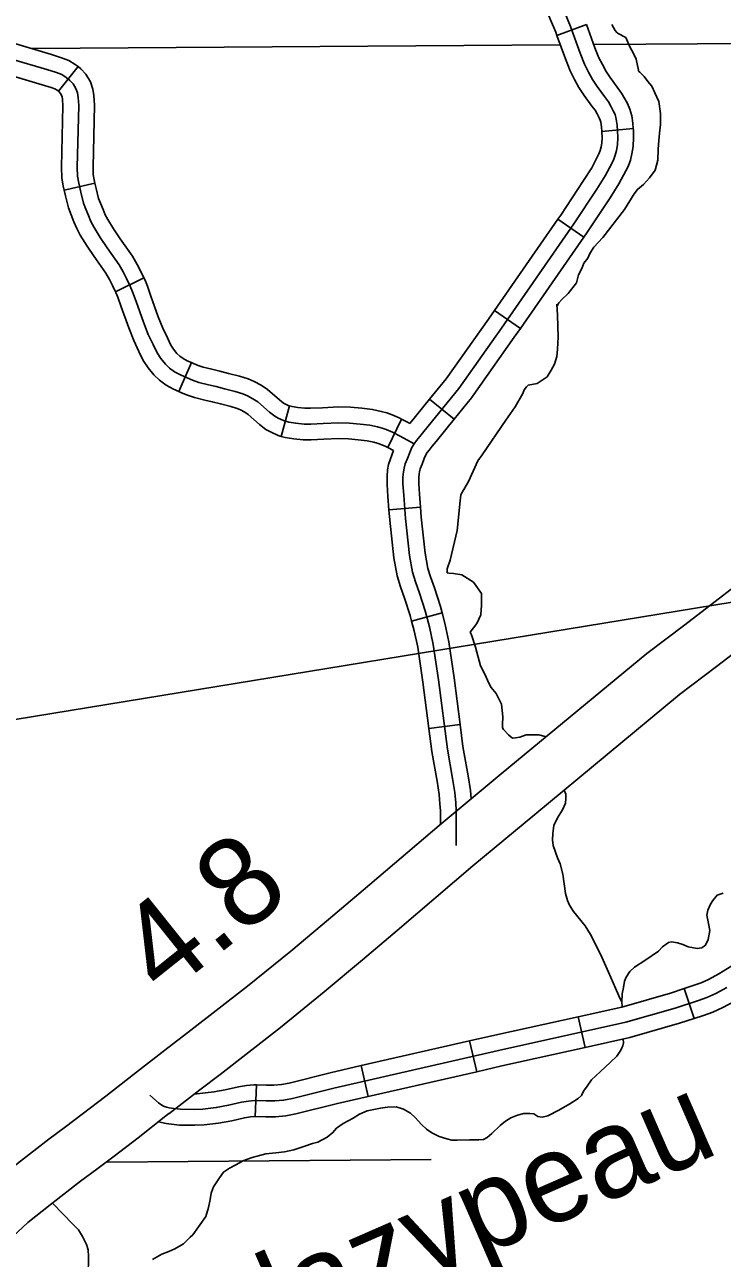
# Model space of a CAD drawing. Extents: x -3711 to 825, y -151 to 1050.
# Drawn here: x -2712.6 to -2675.5, y 376.3 to 442 of the extents above; entities that cross this region are included whole.
import ezdxf

# ---------------------------------------------------------------- set-up
doc = ezdxf.new("R2010")
doc.units = 0
for name, color, linetype in [('Level 10', 7, 'Continuous'), ('Level 32', 7, 'Continuous'), ('Level 35', 7, 'Continuous'), ('Level 48', 7, 'Continuous'), ('Level 5', 7, 'Continuous'), ('R_Dimension', 7, 'Continuous')]:
    doc.layers.add(name, color=color, linetype=linetype)

msp = doc.modelspace()

# ---------------------------------------------------------------- linework, layer by layer
at = {"layer": 'Level 10'}
for p, q in [((-2706.669, 386.248), (-2706.663, 386.253)), ((-2704.949, 384.036), (-2704.943, 384.041))]:
    msp.add_line(p, q, dxfattribs=at)
for points in [[(-2706.663, 386.253), (-2704.999, 387.54), (-2703.925, 388.355), (-2700.75, 390.822), (-2698.456, 392.689), (-2696.451, 394.375), (-2694.609, 395.932), (-2690.561, 399.38), (-2687.248, 402.122), (-2679.507, 408.541), (-2677.486, 410.069), (-2673.235, 413.332)], [(-2671.476, 411.15), (-2675.788, 407.84), (-2677.767, 406.344), (-2685.461, 399.964), (-2688.759, 397.234), (-2692.796, 393.796), (-2694.644, 392.233), (-2696.67, 390.529), (-2699.005, 388.629), (-2702.218, 386.132), (-2703.295, 385.315), (-2704.949, 384.036)], [(-2722.587, 372.439), (-2718.159, 376.666), (-2716.385, 378.412), (-2715.441, 379.293), (-2714.273, 380.373), (-2713, 381.381), (-2711.341, 382.678), (-2710.445, 383.333), (-2709.555, 384.005), (-2708.303, 384.971), (-2706.828, 386.124), (-2706.669, 386.248)], [(-2704.943, 384.041), (-2705.102, 383.917), (-2706.584, 382.758), (-2707.856, 381.778), (-2708.774, 381.084), (-2709.651, 380.443), (-2711.267, 379.179), (-2712.45, 378.242), (-2713.534, 377.24), (-2714.446, 376.389), (-2716.208, 374.654)]]:
    msp.add_lwpolyline(points, dxfattribs=at)
at = {"layer": 'Level 32'}
for p, q in [((-2684.287, 441.438), (-2682.706, 442.01)), ((-2710.826, 438.463), (-2709.775, 439.775)), ((-2681.9, 436.327), (-2680.226, 436.48)), ((-2710.518, 433.202), (-2708.877, 433.567)), ((-2684.239, 431.653), (-2682.858, 430.694)), ((-2707.778, 427.781), (-2706.274, 428.533)), ((-2687.616, 426.793), (-2686.235, 425.834)), ((-2704.418, 422.483), (-2703.735, 424.02)), ((-2698.968, 420.093), (-2698.518, 421.713)), ((-2691.065, 422.067), (-2689.762, 421.005)), ((-2693.289, 419.495), (-2692.557, 421.008)), ((-2693.227, 416.191), (-2691.551, 416.322)), ((-2692.024, 410.265), (-2690.402, 410.707)), ((-2691.108, 404.541), (-2689.441, 404.756)), ((-2676.992, 389.099), (-2677.516, 390.697)), ((-2682.788, 387.56), (-2683.152, 389.201)), ((-2688.559, 386.272), (-2688.933, 387.911)), ((-2694.329, 384.956), (-2694.703, 386.595)), ((-2700.341, 383.893), (-2700.283, 385.573))]:
    msp.add_line(p, q, dxfattribs=at)
for points in [[(-2687.244, 446.261), (-2686.32, 444.967), (-2685.886, 444.437), (-2685.588, 444.014), (-2685.311, 443.579), (-2685.078, 443.216), (-2684.881, 442.868), (-2684.628, 442.273), (-2684.351, 441.612), (-2684.287, 441.438)], [(-2715.774, 442.024), (-2715.738, 441.759), (-2715.654, 441.391), (-2715.555, 441.095), (-2715.376, 440.736), (-2715.148, 440.469), (-2714.991, 440.288), (-2714.661, 439.996), (-2714.401, 439.801), (-2714.059, 439.567), (-2713.644, 439.397), (-2711.679, 438.814), (-2711.203, 438.663), (-2711.019, 438.593), (-2710.891, 438.515), (-2710.826, 438.463)], [(-2714.109, 442.256), (-2714.082, 442.062), (-2714.033, 441.844), (-2713.998, 441.74), (-2713.964, 441.672), (-2713.873, 441.566), (-2713.793, 441.472), (-2713.598, 441.3), (-2713.421, 441.167), (-2713.256, 441.055), (-2713.085, 440.985), (-2711.186, 440.421), (-2710.65, 440.252), (-2710.274, 440.109), (-2709.923, 439.894), (-2709.775, 439.775)], [(-2683.853, 442.6), (-2683.567, 441.918), (-2683.049, 440.486), (-2682.818, 439.899), (-2682.613, 439.49), (-2682.395, 439.095), (-2682.15, 438.713), (-2681.755, 438.181), (-2681.55, 437.908), (-2681.414, 437.663), (-2681.291, 437.431), (-2681.196, 437.226), (-2681.128, 436.981), (-2681.087, 436.667), (-2681.059, 436.367), (-2681.046, 435.999), (-2681.059, 435.617), (-2681.114, 435.317), (-2681.182, 435.057), (-2681.278, 434.798), (-2681.482, 434.389), (-2681.714, 433.966), (-2682.163, 433.257), (-2683.39, 431.402), (-2687.247, 425.851), (-2689.51, 422.645), (-2691.377, 420.354), (-2691.581, 420.095), (-2691.758, 419.877), (-2691.893, 419.693), (-2692.004, 419.508), (-2692.126, 419.236), (-2692.249, 418.922), (-2692.358, 418.635), (-2692.426, 418.404), (-2692.463, 418.2), (-2692.482, 417.928), (-2692.482, 417.559), (-2692.443, 416.957), (-2692.346, 415.714), (-2692.133, 413.753), (-2691.978, 412.859), (-2691.822, 412.354), (-2691.609, 411.752), (-2691.298, 410.8), (-2691.065, 409.946), (-2690.871, 409.014), (-2690.595, 407.13), (-2690.119, 403.449), (-2689.838, 401.876), (-2689.721, 401.138), (-2689.673, 400.594), (-2689.653, 400.186), (-2689.644, 399.759), (-2689.66, 398.307)], [(-2682.706, 442.01), (-2682.263, 440.783), (-2682.049, 440.242), (-2681.869, 439.881), (-2681.673, 439.525), (-2681.458, 439.191), (-2681.081, 438.684), (-2680.843, 438.366), (-2680.675, 438.063), (-2680.538, 437.805), (-2680.404, 437.518), (-2680.302, 437.148), (-2680.251, 436.759), (-2680.226, 436.48)], [(-2684.287, 441.438), (-2683.836, 440.188), (-2683.586, 439.556), (-2683.358, 439.099), (-2683.118, 438.664), (-2682.842, 438.234), (-2682.428, 437.678), (-2682.257, 437.45), (-2682.153, 437.262), (-2682.044, 437.056), (-2681.987, 436.934), (-2681.953, 436.813), (-2681.922, 436.574), (-2681.9, 436.327)], [(-2713.365, 440.191), (-2711.433, 439.618), (-2710.926, 439.458), (-2710.647, 439.351), (-2710.407, 439.204), (-2710.207, 439.044), (-2710.034, 438.858), (-2709.887, 438.618), (-2709.807, 438.378), (-2709.767, 438.138), (-2709.741, 437.711), (-2709.821, 434.418), (-2709.807, 433.951), (-2709.741, 433.578), (-2709.634, 433.098), (-2709.488, 432.511), (-2709.368, 432.191), (-2709.221, 431.845)], [(-2709.775, 439.775), (-2709.633, 439.662), (-2709.36, 439.368), (-2709.12, 438.974), (-2708.989, 438.581), (-2708.931, 438.233), (-2708.899, 437.727), (-2708.98, 434.42), (-2708.969, 434.037), (-2708.916, 433.743), (-2708.877, 433.567)], [(-2710.826, 438.463), (-2710.781, 438.427), (-2710.707, 438.348), (-2710.655, 438.261), (-2710.626, 438.175), (-2710.604, 438.042), (-2710.582, 437.695), (-2710.662, 434.416), (-2710.646, 433.865), (-2710.565, 433.413), (-2710.518, 433.202)], [(-2681.9, 436.327), (-2681.899, 436.313), (-2681.887, 435.998), (-2681.897, 435.707), (-2681.935, 435.499), (-2681.985, 435.31), (-2682.05, 435.132), (-2682.227, 434.779), (-2682.438, 434.394), (-2682.869, 433.714), (-2684.086, 431.874), (-2684.239, 431.653)], [(-2680.226, 436.48), (-2680.22, 436.42), (-2680.205, 435.999), (-2680.222, 435.526), (-2680.293, 435.134), (-2680.379, 434.805), (-2680.505, 434.464), (-2680.737, 433.999), (-2680.989, 433.539), (-2681.458, 432.8), (-2682.694, 430.93), (-2682.858, 430.694)], [(-2708.877, 433.567), (-2708.816, 433.291), (-2708.684, 432.761), (-2708.587, 432.503), (-2708.446, 432.17), (-2708.326, 431.881), (-2708.198, 431.636), (-2707.891, 431.144), (-2707.529, 430.614), (-2706.886, 429.683), (-2706.63, 429.246), (-2706.444, 428.874), (-2706.274, 428.533)], [(-2710.518, 433.202), (-2710.452, 432.905), (-2710.292, 432.261), (-2710.149, 431.88), (-2709.996, 431.519), (-2709.85, 431.168), (-2709.658, 430.8), (-2709.299, 430.225), (-2708.915, 429.662), (-2708.305, 428.78), (-2708.109, 428.444), (-2707.948, 428.122), (-2707.778, 427.781)], [(-2709.221, 431.845), (-2709.088, 431.525), (-2708.928, 431.218), (-2708.595, 430.685), (-2708.222, 430.138), (-2707.596, 429.231), (-2707.369, 428.845), (-2707.196, 428.498), (-2706.996, 428.098), (-2706.876, 427.791), (-2706.69, 427.272), (-2706.29, 426.165), (-2706.037, 425.525), (-2705.784, 424.978), (-2705.571, 424.538), (-2705.371, 424.232), (-2705.131, 423.938), (-2704.904, 423.725), (-2704.638, 423.525), (-2704.332, 423.365), (-2703.972, 423.205), (-2703.692, 423.085), (-2703.346, 422.965), (-2702.839, 422.845), (-2702.426, 422.752), (-2701.987, 422.632), (-2701.414, 422.485), (-2701.014, 422.365), (-2700.761, 422.258), (-2700.468, 422.098), (-2700.215, 421.925), (-2699.589, 421.378), (-2699.309, 421.165), (-2699.122, 421.058), (-2698.842, 420.93), (-2698.564, 420.853), (-2698.193, 420.791), (-2697.75, 420.752), (-2697.39, 420.752), (-2696.724, 420.779), (-2695.898, 420.819), (-2695.325, 420.805), (-2694.766, 420.752), (-2694.246, 420.685), (-2693.833, 420.605), (-2693.593, 420.539), (-2693.38, 420.459), (-2693.047, 420.312), (-2692.634, 420.112), (-2691.893, 419.693)], [(-2684.239, 431.653), (-2687.616, 426.793)], [(-2682.858, 430.694), (-2686.235, 425.834)], [(-2706.274, 428.533), (-2706.227, 428.44), (-2706.089, 428.087), (-2705.899, 427.556), (-2705.504, 426.462), (-2705.264, 425.856), (-2705.024, 425.338), (-2704.837, 424.953), (-2704.691, 424.729), (-2704.515, 424.513), (-2704.362, 424.369), (-2704.188, 424.238), (-2703.966, 424.122), (-2703.735, 424.02)], [(-2707.778, 427.781), (-2707.765, 427.757), (-2707.664, 427.496), (-2707.481, 426.987), (-2707.076, 425.867), (-2706.81, 425.193), (-2706.544, 424.618), (-2706.304, 424.124), (-2706.05, 423.735), (-2705.747, 423.364), (-2705.447, 423.081), (-2705.088, 422.812), (-2704.697, 422.608), (-2704.418, 422.483)], [(-2687.616, 426.793), (-2687.936, 426.333), (-2690.18, 423.154), (-2691.065, 422.067)], [(-2686.235, 425.834), (-2686.559, 425.369), (-2688.84, 422.137), (-2689.762, 421.005)], [(-2703.735, 424.02), (-2703.635, 423.975), (-2703.388, 423.87), (-2703.111, 423.773), (-2702.65, 423.664), (-2702.223, 423.568), (-2701.772, 423.444), (-2701.189, 423.295), (-2700.729, 423.157), (-2700.396, 423.017), (-2700.028, 422.816), (-2699.699, 422.591), (-2699.057, 422.03), (-2698.843, 421.867), (-2698.738, 421.807), (-2698.553, 421.722), (-2698.518, 421.713)], [(-2704.418, 422.483), (-2704.308, 422.435), (-2703.996, 422.301), (-2703.581, 422.157), (-2703.029, 422.026), (-2702.63, 421.936), (-2702.202, 421.819), (-2701.639, 421.675), (-2701.299, 421.573), (-2701.127, 421.5), (-2700.908, 421.381), (-2700.731, 421.259), (-2700.121, 420.727), (-2699.774, 420.463), (-2699.507, 420.31), (-2699.131, 420.138), (-2698.968, 420.093)], [(-2698.518, 421.713), (-2698.382, 421.675), (-2698.087, 421.626), (-2697.713, 421.592), (-2697.407, 421.592), (-2696.761, 421.618), (-2695.909, 421.66), (-2695.276, 421.645), (-2694.672, 421.587), (-2694.113, 421.516), (-2693.64, 421.424), (-2693.333, 421.339), (-2693.063, 421.237), (-2692.694, 421.075), (-2692.557, 421.008)], [(-2691.065, 422.067), (-2692.112, 420.782)], [(-2692.557, 421.008), (-2692.244, 420.857), (-2692.112, 420.782)], [(-2689.762, 421.005), (-2690.721, 419.828), (-2690.925, 419.57), (-2691.093, 419.363), (-2691.192, 419.228), (-2691.257, 419.119), (-2691.351, 418.91), (-2691.465, 418.619), (-2691.561, 418.367), (-2691.607, 418.21), (-2691.627, 418.096), (-2691.642, 417.898), (-2691.642, 417.586), (-2691.605, 417.017), (-2691.551, 416.322)], [(-2698.968, 420.093), (-2698.746, 420.031), (-2698.3, 419.957), (-2697.787, 419.911), (-2697.374, 419.911), (-2696.687, 419.939), (-2695.888, 419.977), (-2695.375, 419.966), (-2694.859, 419.916), (-2694.38, 419.855), (-2694.026, 419.786), (-2693.854, 419.739), (-2693.698, 419.68), (-2693.4, 419.549), (-2693.289, 419.495)], [(-2692.986, 419.348), (-2693.155, 418.904), (-2693.245, 418.597), (-2693.298, 418.305), (-2693.323, 417.958), (-2693.323, 417.532), (-2693.282, 416.898), (-2693.227, 416.191)], [(-2693.289, 419.495), (-2692.986, 419.348)], [(-2693.227, 416.191), (-2693.183, 415.636), (-2692.966, 413.635), (-2692.797, 412.663), (-2692.621, 412.09), (-2692.405, 411.481), (-2692.104, 410.559), (-2692.024, 410.265)], [(-2691.551, 416.322), (-2691.509, 415.792), (-2691.3, 413.87), (-2691.158, 413.055), (-2691.024, 412.618), (-2690.813, 412.023), (-2690.493, 411.041), (-2690.402, 410.707)], [(-2690.402, 410.707), (-2690.248, 410.142), (-2690.043, 409.16), (-2689.762, 407.245), (-2689.441, 404.756)], [(-2692.024, 410.265), (-2691.883, 409.75), (-2691.699, 408.867), (-2691.427, 407.015), (-2691.108, 404.541)], [(-2691.108, 404.541), (-2690.95, 403.321), (-2690.667, 401.736), (-2690.556, 401.035), (-2690.512, 400.537), (-2690.494, 400.157), (-2690.484, 399.754), (-2690.488, 399.44)], [(-2689.441, 404.756), (-2689.288, 403.577), (-2689.009, 402.015), (-2688.887, 401.241), (-2688.847, 400.798)], [(-2677.516, 390.697), (-2677.031, 390.856), (-2676.618, 391.003), (-2676.213, 391.188), (-2675.663, 391.489), (-2674.981, 391.901), (-2674.499, 392.22), (-2674.226, 392.408), (-2673.955, 392.61), (-2673.28, 393.16), (-2672.765, 393.586)], [(-2676.992, 389.099), (-2676.486, 389.265), (-2675.986, 389.444), (-2675.46, 389.683), (-2674.824, 390.032), (-2674.083, 390.48), (-2673.558, 390.826), (-2673.247, 391.041), (-2672.921, 391.283), (-2672.13, 391.929)], [(-2705.965, 385.02), (-2705.487, 384.615), (-2705.378, 384.518), (-2705.234, 384.445), (-2705.064, 384.377), (-2704.922, 384.349), (-2704.686, 384.306), (-2704.332, 384.273), (-2703.568, 384.268), (-2703.131, 384.284), (-2702.419, 384.366), (-2701.769, 384.485), (-2701.075, 384.648), (-2700.707, 384.702), (-2700.384, 384.735), (-2699.762, 384.714), (-2699.311, 384.714), (-2698.839, 384.757), (-2698.367, 384.842), (-2696.157, 385.401), (-2687.402, 387.398), (-2680.621, 388.901), (-2678.003, 389.653), (-2676.758, 390.061), (-2676.302, 390.224), (-2675.836, 390.435), (-2675.244, 390.76)], [(-2683.152, 389.201), (-2680.828, 389.716), (-2678.25, 390.456), (-2677.516, 390.697)], [(-2688.933, 387.911), (-2687.586, 388.218), (-2683.152, 389.201)], [(-2682.788, 387.56), (-2680.414, 388.086), (-2677.756, 388.849), (-2676.992, 389.099)], [(-2694.703, 386.595), (-2688.933, 387.911)], [(-2688.559, 386.272), (-2687.217, 386.578), (-2682.788, 387.56)], [(-2700.283, 385.573), (-2699.747, 385.554), (-2699.349, 385.554), (-2698.953, 385.59), (-2698.545, 385.664), (-2696.353, 386.218), (-2694.703, 386.595)], [(-2694.329, 384.956), (-2688.559, 386.272)], [(-2703.605, 385.076), (-2702.543, 385.198), (-2701.941, 385.308), (-2701.233, 385.475), (-2700.81, 385.537), (-2700.412, 385.577), (-2700.283, 385.573)], [(-2700.341, 383.893), (-2699.776, 383.873), (-2699.273, 383.873), (-2698.725, 383.923), (-2698.188, 384.021), (-2695.96, 384.583), (-2694.329, 384.956)], [(-2705.499, 383.607), (-2705.08, 383.523), (-2704.8, 383.472), (-2704.373, 383.433), (-2703.556, 383.428), (-2703.067, 383.445), (-2702.295, 383.534), (-2701.597, 383.662), (-2700.918, 383.822), (-2700.603, 383.868), (-2700.356, 383.893), (-2700.341, 383.893)]]:
    msp.add_lwpolyline(points, dxfattribs=at)
at = {"layer": 'Level 35'}
for points in [[(-2678.807, 436.409), (-2678.78, 436.671), (-2678.78, 437.287), (-2678.858, 437.915), (-2679.078, 438.379), (-2679.245, 438.738), (-2679.449, 438.993), (-2679.65, 439.255), (-2679.883, 439.488), (-2679.94, 439.539), (-2679.952, 439.584), (-2680.069, 440.172), (-2680.244, 440.55), (-2680.388, 440.79), (-2680.62, 441.32), (-2681.065, 441.563), (-2681.105, 441.591), (-2681.187, 441.696), (-2681.357, 442.013)], [(-2684.294, 427.132), (-2684.278, 427.051), (-2684.194, 427.194), (-2684.02, 427.379), (-2683.692, 427.707), (-2683.249, 428.261), (-2683.141, 428.695), (-2682.963, 429.036), (-2682.848, 429.306), (-2682.645, 429.576), (-2682.543, 429.821), (-2682.33, 430.17), (-2681.838, 430.677), (-2680.688, 432.165), (-2680.173, 433.012), (-2680, 433.236), (-2679.674, 433.5), (-2679.367, 433.855), (-2679.068, 434.273), (-2678.918, 434.8), (-2678.897, 435.375), (-2678.867, 435.839), (-2678.807, 436.409)], [(-2684.918, 404.125), (-2685.249, 404.199), (-2685.529, 404.199), (-2685.934, 404.199), (-2686.27, 404.073), (-2686.49, 404.041), (-2686.645, 404.024), (-2686.73, 404.074), (-2686.871, 404.197), (-2687.132, 404.492), (-2687.181, 404.583), (-2687.181, 404.763), (-2687.162, 405.158), (-2687.243, 405.84), (-2687.528, 406.41), (-2687.794, 406.726), (-2687.93, 406.999), (-2688.113, 407.397), (-2688.356, 407.883), (-2688.618, 408.871), (-2688.833, 409.536), (-2688.901, 409.672), (-2688.736, 409.896), (-2688.553, 410.131), (-2688.34, 410.6), (-2688.31, 411.106), (-2688.31, 411.729), (-2688.735, 412.336), (-2689.355, 412.724), (-2689.801, 412.798), (-2690.034, 412.818), (-2690.13, 412.828), (-2690.135, 412.916), (-2690.129, 413.035), (-2690.107, 413.101), (-2689.976, 413.495), (-2689.601, 415.087), (-2689.446, 416.664), (-2689.402, 416.984), (-2689.369, 417.06), (-2688.992, 417.699), (-2688.49, 418.786), (-2688.273, 419.112), (-2687.001, 420.963), (-2686.514, 421.659), (-2686.094, 422.379), (-2686.024, 422.579), (-2685.902, 422.725), (-2685.829, 422.809), (-2685.813, 422.812), (-2685.333, 422.902), (-2684.811, 423.268), (-2684.598, 423.609), (-2684.424, 423.933), (-2684.287, 424.344), (-2684.261, 424.731), (-2684.225, 425.379), (-2684.26, 426.552), (-2684.294, 427.132)], [(-2682.507, 393.576), (-2682.787, 394.031), (-2683.402, 394.795), (-2683.618, 395.144), (-2683.734, 395.393), (-2683.833, 395.759), (-2683.966, 396.789), (-2684.116, 397.337), (-2684.249, 397.653), (-2684.481, 398.318), (-2684.531, 398.617), (-2684.514, 398.949), (-2684.448, 399.381), (-2684.265, 399.78), (-2683.999, 400.212), (-2683.833, 400.561), (-2683.817, 400.81), (-2683.817, 401.043), (-2683.902, 401.256)], [(-2675.447, 395.782), (-2675.647, 395.699), (-2675.764, 395.666), (-2675.997, 395.382), (-2676.113, 395.199), (-2676.263, 394.866), (-2676.313, 394.6), (-2676.213, 394.166), (-2676.146, 393.783), (-2676.246, 393.317), (-2676.379, 393.017), (-2676.579, 392.867), (-2676.829, 392.834), (-2677.295, 392.917), (-2677.594, 393.05), (-2677.877, 393.134), (-2678.194, 393.184), (-2678.343, 393.15), (-2678.477, 393.067), (-2678.676, 392.917), (-2678.876, 392.684), (-2679.608, 392.184), (-2680.158, 391.835), (-2680.407, 391.601), (-2680.607, 391.302), (-2680.694, 391.089), (-2680.753, 390.757), (-2680.811, 390.425), (-2680.831, 389.976), (-2680.824, 389.769)], [(-2680.831, 389.976), (-2680.987, 390.308), (-2681.163, 390.718), (-2681.545, 391.563), (-2681.976, 392.527), (-2682.507, 393.576)], [(-2680.768, 388.007), (-2680.753, 387.809), (-2680.786, 387.642), (-2680.836, 387.542), (-2680.886, 387.425), (-2681.102, 387.092), (-2681.435, 386.776), (-2681.984, 386.259), (-2682.45, 385.843), (-2682.684, 385.51), (-2682.867, 385.243), (-2682.983, 385.01), (-2683.166, 384.844), (-2683.599, 384.561), (-2684.181, 384.227), (-2684.764, 383.928), (-2685.08, 383.861), (-2685.297, 383.894), (-2685.513, 384.028), (-2685.729, 384.044), (-2686.046, 384.044), (-2686.379, 383.961), (-2686.745, 383.811), (-2687.028, 383.644), (-2687.311, 383.411), (-2687.76, 382.978), (-2688.01, 382.762), (-2688.193, 382.662), (-2688.442, 382.645), (-2688.942, 382.645), (-2689.591, 382.628), (-2689.89, 382.628), (-2690.14, 382.695), (-2690.556, 382.828), (-2690.556, 382.828), (-2690.939, 383.011), (-2691.222, 383.211), (-2691.505, 383.461), (-2691.838, 383.828), (-2692.087, 384.061), (-2692.454, 384.277), (-2692.853, 384.394), (-2693.303, 384.377), (-2693.685, 384.327), (-2694.384, 384.194), (-2694.8, 384.011), (-2695.133, 383.794), (-2695.666, 383.511), (-2696.016, 383.261), (-2696.215, 383.028), (-2696.515, 382.795), (-2697.014, 382.528), (-2697.297, 382.445), (-2697.763, 382.295), (-2698.296, 382.112), (-2698.795, 382.012), (-2699.244, 381.962), (-2699.777, 381.895), (-2700.243, 381.779), (-2700.509, 381.712), (-2701.009, 381.529), (-2701.025, 381.512), (-2701.375, 381.313), (-2701.724, 381.146), (-2702.041, 380.929), (-2702.257, 380.63), (-2702.573, 380.147), (-2702.673, 379.863), (-2702.7, 379.799)], [(-2702.7, 379.799), (-2702.751, 379.474), (-2702.827, 379.042), (-2702.977, 378.559), (-2703.36, 378.01), (-2703.676, 377.593), (-2703.809, 377.46), (-2704.158, 377.11), (-2704.625, 376.844), (-2704.941, 376.694), (-2705.324, 376.561), (-2705.806, 376.277)], [(-2708.569, 371.214), (-2708.881, 372.854), (-2709.032, 373.804), (-2709.182, 374.453), (-2709.318, 375.026), (-2709.333, 375.403), (-2709.243, 375.78), (-2709.228, 376.022), (-2709.213, 376.444), (-2709.243, 376.791), (-2709.333, 377.078), (-2709.544, 377.5), (-2709.755, 377.847), (-2710.057, 378.156), (-2711.124, 379.254)]]:
    msp.add_lwpolyline(points, dxfattribs=at)
at = {"layer": 'Level 5'}
for points in [[(-2684.134, 440.934), (-2712.223, 440.748)], [(-2640.231, 440.903), (-2657.522, 441.111), (-2682.313, 440.947)], [(-2708.229, 381.463), (-2690.982, 381.603)]]:
    msp.add_lwpolyline(points, dxfattribs=at)
at = {"layer": 'R_Dimension'}
msp.add_line((-2478.38, 443.501), (-2866.636, 379.848), dxfattribs=at)

# ---------------------------------------------------------------- texts
at = {"layer": 'Level 35'}
msp.add_text('Glazypeau', height=4.7343, rotation=23.57864, dxfattribs=at).set_placement((-2703.276, 369.881))
at = {"layer": 'Level 48'}
msp.add_text('4.8', height=4.7343, rotation=38.62679, dxfattribs=at).set_placement((-2705.215, 390.165))

doc.saveas('drawing.dxf')
